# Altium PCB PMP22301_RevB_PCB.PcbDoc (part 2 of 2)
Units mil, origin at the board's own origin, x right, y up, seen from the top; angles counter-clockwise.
Board outline 2805 x 3100 mil, 4 copper layers (Top Layer, Signal Layer 1, Signal Layer 2, Bottom Layer), stack 61.2 mil thick; 104 components, 74 nets, 288 pads, 112 vias.
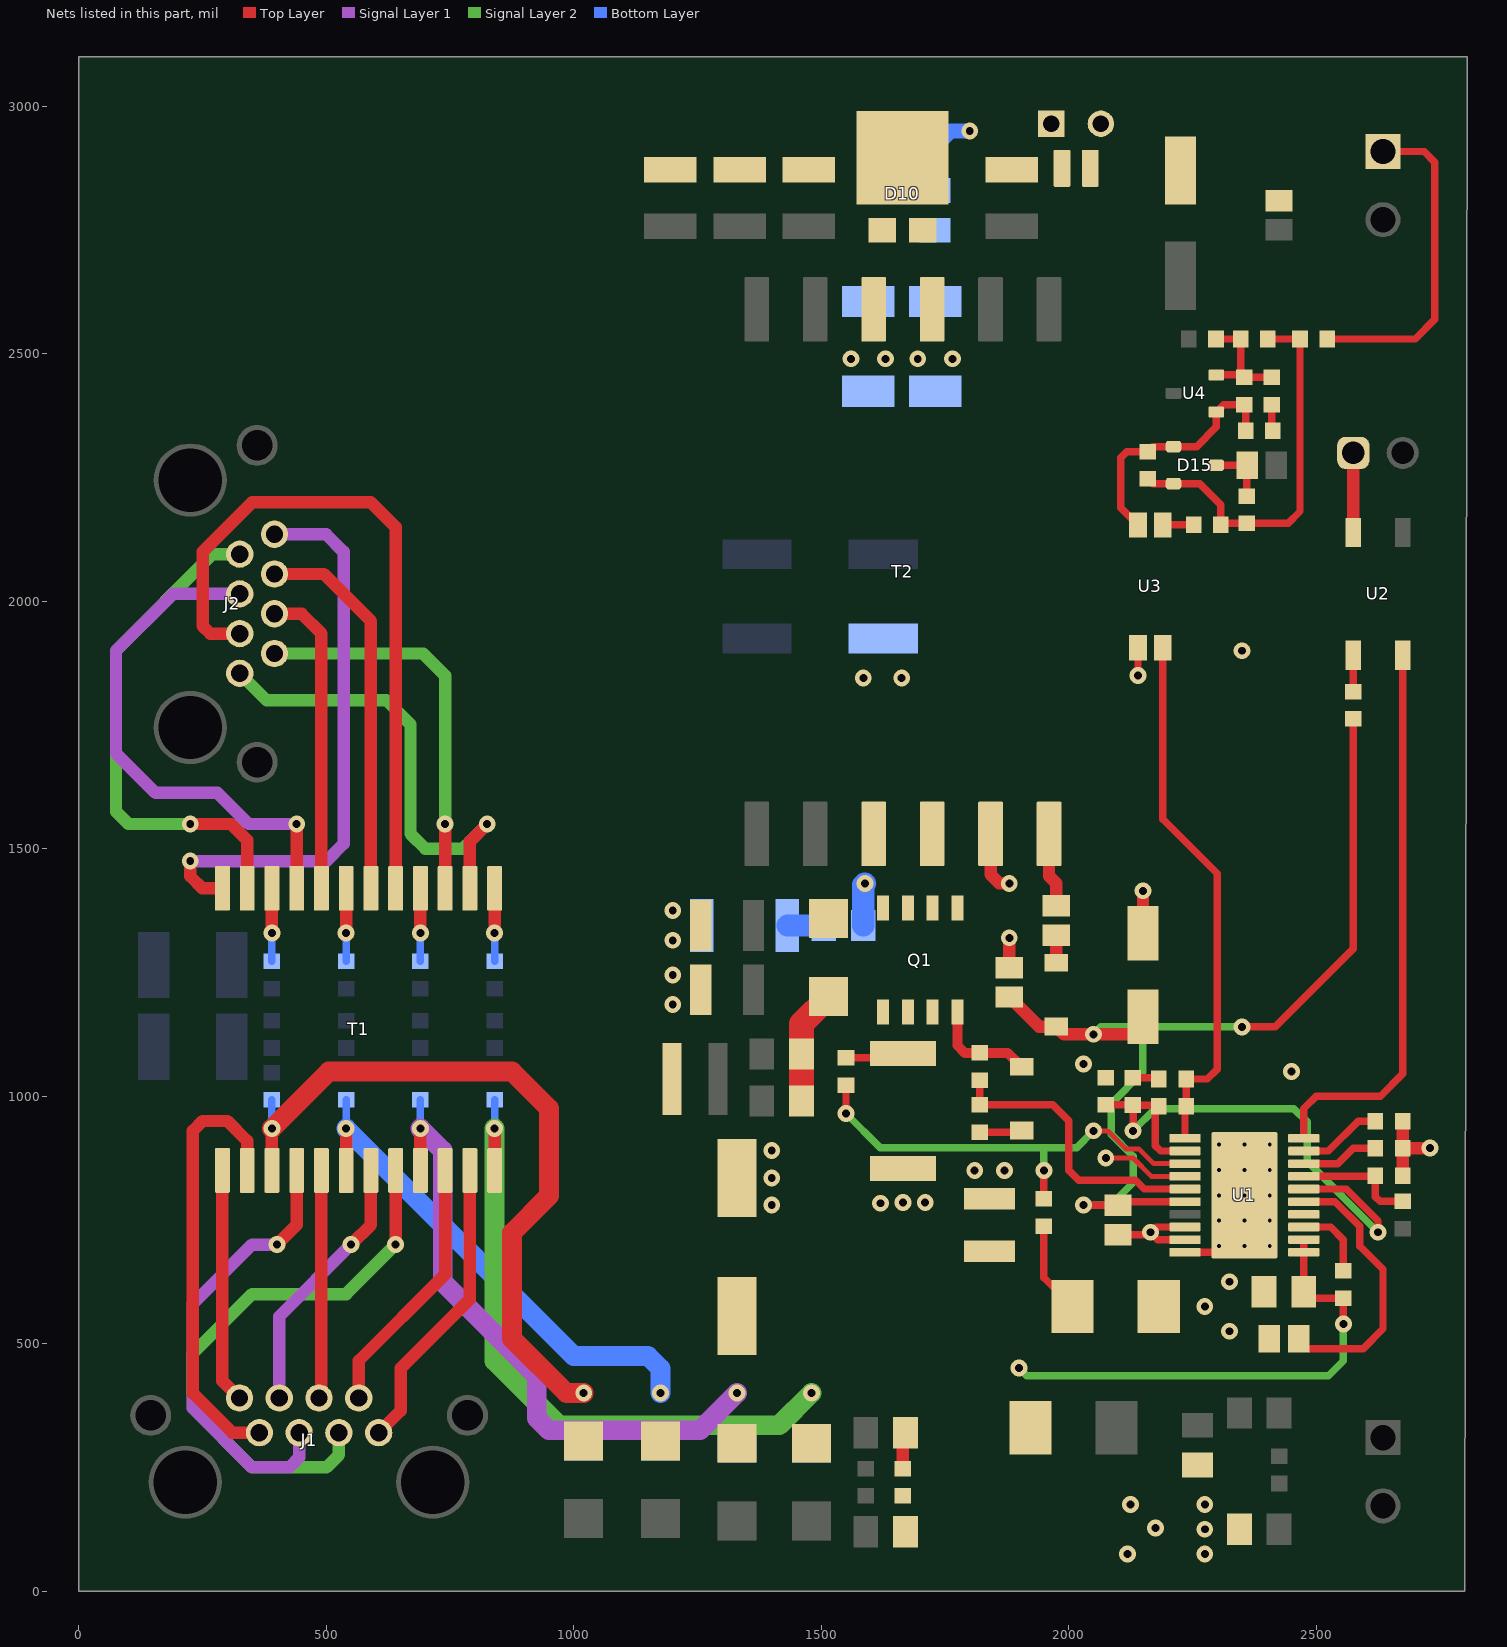
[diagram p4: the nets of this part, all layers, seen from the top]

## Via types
v1: diameter 34, hole 16, Top Layer to Bottom Layer, 97 vias
v2: diameter 19.68, hole 7.87, Top Layer to Bottom Layer, tented both sides, 12 vias
v3: diameter 19.68, hole 7.87, Top Layer to Bottom Layer, 3 vias

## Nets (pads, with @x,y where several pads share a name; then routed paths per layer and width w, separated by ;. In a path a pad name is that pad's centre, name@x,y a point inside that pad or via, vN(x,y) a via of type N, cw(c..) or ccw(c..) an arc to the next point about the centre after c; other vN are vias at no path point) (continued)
NetC12_1: C12.1 C18.2 C19.2 C20.2 C21.2 D10.3 J4.1 L6.1 | length 171.5
  Bottom Layer w30: C12.1@1730,2830 1730,2918.47 1761.53,2950 v1(1800,2950)
NetC12_2: C12.2 R9.2 R10.2
NetC16_1: C16.1 D11.1 R11.1 | length 234
  Top Layer w50: R11.1@1460,990 C16.1@1460,1085 1460,1146.26 D11.1@1515,1201.26
NetC17_1: C17.1 C22.1 J4.2 J5.1 L6.2 R26.2 | length 665.4
  Top Layer w15: R26.2@2522.56,2530 2700,2530 2740,2570 2740,2887.52 2718.62,2908.9 J5.1@2635,2908.9
NetC23_1: C23.1 D11.2 Q1.5 Q1.6 Q1.7 Q1.8 T2.3 T2.4 | length 86.3
  Bottom Layer w45: C23.1@1585,1345 1585,1426.93 v1(1588.07,1430)
NetC23_2: C23.2 R14.2 | length 73.4
  Bottom Layer w45: R14.2@1431.61,1345 C23.2@1505,1345
NetC30_1: C30.1 C32.1 R32.1 R34.1 U4.2 | length 237.3
  Top Layer w15: R34.1@2297.56,2530 R32.1@2347.44,2530 2347.44,2460.12 C30.1@2350.16,2457.4 ; U4.2@2298.31,2457.4 C30.1@2350.16,2457.4 ; C32.1@2410,2452.56 C30.1@2355,2452.56 C30.1@2350.16,2457.4
NetC30_2: C30.2 D15.1 R29.2 R33.2 U3.2 U4.1 | length 516.1
  Top Layer w15: U3.2@2140,2154.02 2105,2189.02 2105,2290 2117.56,2302.56 R29.2@2160,2302.56 2169.84,2312.4 D15.1@2211.69,2312.4 2258.35,2312.4 2298.31,2352.36 U4.1@2298.31,2382.6 2313.15,2397.44 C30.2@2355,2397.44 2357.44,2395 R33.2@2357.44,2345
NetC31_1: C31.1 R30.1 U1.1 U3.4 | length 1088.7
  Top Layer w15: U3.4@2190,1905.98 2190,1560 2300,1450 2300,1054.68 2280,1034.68 C31.1@2237.24,1034.68 R30.1@2237.24,979.68 2234.92,977.36 U1.1@2234.92,914.84
NetC31_2: C31.2 R27.2 | length 53.5
  Top Layer w15: R27.2@2129.69,1037.24 2179.57,1037.24 C31.2@2182.13,1034.68
NetC32_2: C32.2 R33.1 | length 53.5
  Top Layer w15: C32.2@2410,2397.44 2410,2347.56 R33.1@2412.56,2345
NetC33_1: C33.1 D15.3 R28.1 | length 124.8
  Top Layer w15: D15.3@2298.31,2275 C33.1@2360.47,2275 2360,2274.53 R28.1@2360,2212.56
NetD10_1: D10.1 D10.2 R9.1 R10.1 T2.9 T2.10
  other v1: 1560,2490 1630,2490 1695,2490 1765,2490
NetD12_1: D12.1 R15.2 | length 86.3
  Top Layer w15: R15.2@1820,927.44 1901.91,927.44 D12.1@1905,930.53
NetD12_2: D12.2 Q1.4 R12.2 | length 215.2
  Top Layer w20: Q1.4@1775,1169.88 1775,1102.56 1790,1087.56 R12.2@1820,1087.56 1876.91,1087.56 D12.2@1905,1059.47
NetD13_2: D13.2 R13.2 | length 56
  Top Layer w25: D13.2@1975,1269.47 R13.2@1975,1325.47
NetD15_2: D15.2 R26.1 R28.2 R29.1 R31.2 R32.2 | length 793.6
  Top Layer w15: R29.1@2160,2247.44 2169.84,2237.6 D15.2@2211.69,2237.6 2265,2237.6 2307.56,2195.04 R31.2@2307.56,2155 2310,2157.44 R28.2@2360,2157.44 2443.43,2157.44 2467.44,2181.46 R26.1@2467.44,2530 R32.2@2402.56,2530
NetJ1_1: J1.1 T1.23 | length 606.3
  Top Layer w25: J1.1@605.63,320 650,364.37 650,450 790,590 T1.23@790,849.96
NetJ1_2: J1.2 T1.22 | length 532.2
  Top Layer w25: J1.2@565.47,390.08 565.47,465.47 740,640 T1.22@740,849.96
NetJ1_3: J1.3 T1.20 | length 1161.3
  Top Layer w25: v1(640,700) T1.20@640,849.96
  Signal Layer 2 w25: J1.3@525.31,320 525.31,275.31 500,250 350,250 230,370 230,480 350,600 540,600 v1(640,700)
NetJ1_4: J1.4 T1.17 | length 461.9
  Top Layer w25: J1.4@485.16,390.08 490,394.92 T1.17@490,849.96
NetJ1_5: J1.5 T1.16 | length 919.2
  Top Layer w25: v1(400,700) 440,740 T1.16@440,849.96
  Signal Layer 1 w25: v1(400,700) 350,700 230,580 230,370 350,250 425,250 445,270 J1.5@445,320
NetJ1_6: J1.6 T1.19 | length 536.6
  Top Layer w25: v1(550.04,700) 590,739.96 T1.19@590,849.96
  Signal Layer 1 w25: J1.6@404.84,390.08 404.84,554.8 v1(550.04,700)
NetJ1_7: J1.7 T1.14 | length 892.7
  Top Layer w25: T1.14@340,849.96 340,910 300,950 250,950 230,930 230,400 310,320 J1.7@364.68,320
NetJ1_8: J1.8 T1.13 | length 474.2
  Top Layer w25: T1.13@290,849.96 290,424.61 J1.8@324.53,390.08
NetJ2_1: J2.1 T1.2 | length 941.6
  Top Layer w25: T1.2@790,1420.04 790,1515 v1(825,1550)
  Signal Layer 2 w25: J2.1@325,1854.37 379.37,1800 621.3,1800 670,1751.3 670,1530 700,1500 775,1500 v1(825,1550)
NetJ2_2: J2.2 T1.3 | length 793.3
  Top Layer w25: T1.3@740,1420.04 v1(740,1550)
  Signal Layer 2 w25: J2.2@395.08,1894.53 695.47,1894.53 740,1850 v1(740,1550)
NetJ2_3: J2.3 T1.5 | length 1413.4
  Top Layer w25: J2.3@325,1934.69 265.31,1934.69 250,1950 250,2100 350,2200 590,2200 640,2150 T1.5@640,1420.04
NetJ2_4: J2.4 T1.8 | length 626.4
  Top Layer w25: J2.4@395.08,1974.84 450.16,1974.84 490,1935 T1.8@490,1420.04
NetJ2_5: J2.5 T1.9 | length 1058.9
  Top Layer w25: T1.9@440,1420.04 v1(440,1550)
  Signal Layer 1 w25: J2.5@325,2015 190,2015 75,1900 75,1692.83 155,1612.83 280,1612.83 342.83,1550 v1(440,1550)
NetJ2_6: J2.6 T1.6 | length 774.3
  Top Layer w25: J2.6@395.08,2055.16 494.84,2055.16 590,1960 T1.6@590,1420.04
NetJ2_7: J2.7 T1.11 | length 1042.3
  Top Layer w25: v1(225,1550) 307.63,1550 340,1517.63 T1.11@340,1420.04
  Signal Layer 2 w25: v1(225,1550) 100,1550 75,1575 75,1900 270.32,2095.32 J2.7@325,2095.32
NetJ2_8: J2.8 T1.12 | length 1174.8
  Top Layer w25: v1(225,1475) 225,1444.37 249.33,1420.04 T1.12@290,1420.04
  Signal Layer 1 w25: v1(225,1475) 500,1475 535,1510 535,2100 499.53,2135.47 J2.8@395.08,2135.47
NetJ6_1: J6.1 U2.4 | length 161
  Top Layer w25: U2.4@2575,2139.02 J6.1@2575,2300
NetQ1_1: Q1.1 Q1.2 Q1.3 R17.1 R18.2 | length 118.6
  Top Layer w15: R18.2@1550,1077.56 1656.42,1077.56 R17.1@1665,1086.14
NetR1_1: R1.1 T1.1 | length 147.5
  Top Layer w25: v1(840,1330) T1.1@840,1420.04
  Bottom Layer w15: R1.1@840,1272.56 v1(840,1330)
NetR2_1: R2.1 T1.4 | length 147.5
  Top Layer w25: v1(690,1330) T1.4@690,1420.04
  Bottom Layer w15: R2.1@690,1272.56 v1(690,1330)
NetR3_1: R3.1 T1.7 | length 147.5
  Top Layer w25: v1(540,1330) T1.7@540,1420.04
  Bottom Layer w15: R3.1@540,1272.56 v1(540,1330)
NetR8_2: R8.2 T1.10 | length 147.5
  Top Layer w25: v1(390,1330) T1.10@390,1420.04
  Bottom Layer w15: R8.2@390,1272.56 v1(390,1330)
NetR12_1: R12.1 R15.1 U1.5 | length 593.8
  Top Layer w15: R12.1@1820,1032.44 R15.1@1820,982.56 1967.44,982.56 2000,950 2000,850 2020,830 2135,830 2152.52,812.48 U1.5@2234.92,812.48
NetR13_1: R13.1 T2.6 | length 151.7
  Top Layer w25: T2.6@1960.28,1530.08 1960.28,1444.72 1975,1430 R13.1@1975,1384.53
NetR16_1: R16.1 R20.1 U1.17 | length 246.1
  Top Layer w15: U1.17@2475.08,838.07 2618.78,838.07 R20.1@2619.57,838.86 2619.57,796.93 2628.94,787.56 R16.1@2675,787.56
NetR18_1: R18.1 R21.1 U1.3 | length 917
  Top Layer w10: v1(2050,930) 2078.9,930 2116.02,892.87 2142.6,892.87 2171.81,863.66 U1.3@2234.92,863.66
  Top Layer w15: v1(1550,965) R18.1@1550,1022.44 ; R21.1@1950,792.56 v1(1950,850)
  Signal Layer 2 w15: v1(1550,965) 1618.84,896.16 1947.5,896.16 ; v1(1950,850) 1950,893.66 1947.5,896.16 ; v1(2050,930) 2016.16,896.16 1947.5,896.16
NetR19_1: R19.1 U1.19 | length 169.5
  Top Layer w15: U1.19@2475.08,889.25 2524.25,889.25 2584.68,949.68 R19.1@2619.57,949.68
NetR22_2: R22.2 U1.18 | length 157.3
  Top Layer w15: U1.18@2475.08,863.66 2543.66,863.66 2574.68,894.68 R22.2@2619.57,894.68
NetR23_1: R23.1 U1.15 | length 555.4
  Top Layer w15: R23.1@2464.53,510 2484.53,490 2595,490 2635,530 2635,650 2587.8,697.2 2587.8,737.2 2538.11,786.89 U1.15@2475.08,786.89
NetR24_1: R24.1 U2.1 | length 73.4
  Top Layer w15: R24.1@2575,1817.56 U2.1@2575,1890.98
NetR25_1: R25.1 U1.13 | length 153.2
  Top Layer w15: U1.13@2475.08,735.71 2529.29,735.71 2554.69,710.31 R25.1@2554.69,647.24
NetR31_1: R31.1 U3.1 | length 62.8
  Top Layer w15: U3.1@2190,2154.02 2190.98,2155 R31.1@2252.44,2155
PGND: C7.1 C13.2 C14.2 C15.2 C24.2 C25.1 C26.2 C27.2 C28.2 C34.2 L3.1 R14.1 R17.2 R19.2 R20.2 R22.1 T2.5 U1.4 U1.8 U1.9 U3.3 | length 888.5
  Top Layer w10: v1(2075,875) 2130,875 2166.93,838.07 U1.4@2234.92,838.07
  Top Layer w15: C28.2@2099.69,720.16 2160.16,720.16 v1(2165,725) ; v1(2140,1850) U3.3@2140,1905.98 ; U1.9@2234.92,710.12 2179.88,710.12 v1(2165,725) ; U1.8@2234.92,735.71 2175.71,735.71 v1(2165,725)
  Top Layer w25: T2.5@1842.17,1530.08 1842.17,1447.83 1860,1430 v1(1880,1430) ; C26.2@1880,1259.53 v1(1880,1320) ; C27.2@2150,1329.65 v1(2150,1415) ; R20.2@2674.69,838.86 R22.1@2674.69,894.68 ; R19.2@2674.69,949.68 R22.1@2674.69,894.68 ; v1(2730,895) 2675,895 R22.1@2674.69,894.68
  other v1: 2275,75 2275,125 2275,175 1400,780 1620,783.7 1665,785 1710,785 1400,835 1810,850 1870,850 1400,890 2450,1050 2030,1065 1200,1185 1200,1245 1200,1315 1200,1375 1585,1845 1662.5,1845 2350,1900
PPD: U1.14
PR12: C2.2 D2.2 D6.1 T1.24 | length 1333.3
  Top Layer w25: T1.24@840,849.96 v1(840,935)
  Signal Layer 2 w40: v1(840,935) 840,465 970,335 1415,335 v1(1480,400)
  Bottom Layer w15: v1(840,935) C2.2@840,992.44
PR36: C3.2 D3.2 D7.1 T1.21 | length 1271.2
  Top Layer w25: T1.21@690,849.96 v1(690,935)
  Signal Layer 1 w40: v1(690,935) 735,890 735,625 925.04,434.96 925.04,349.96 950,325 1255,325 v1(1330,400)
  Bottom Layer w15: v1(690,935) C3.2@690,992.44
PR45: C4.2 D5.2 D9.1 T1.18 | length 1028.4
  Top Layer w25: T1.18@540,849.96 v1(540,935)
  Bottom Layer w15: v1(540,935) C4.2@540,992.44
  Bottom Layer w40: v1(540,935) 1000,475 1150,475 1175,450 v1(1175,400)
PR78: C5.2 D4.2 D8.1 T1.15 | length 1467.8
  Top Layer w25: T1.15@390,849.96 v1(390,935)
  Top Layer w40: v1(390,935) 505,1050 875,1050 950,975 950,798.9 875,723.9 875,510 985,400 v1(1020,400)
  Bottom Layer w15: v1(390,935) C5.2@390,992.44
T2P: U1.20 U2.2 | length 1139.1
  Top Layer w15: U1.20@2475.08,914.84 2475.08,975.08 2500,1000 2630,1000 2675,1045 U2.2@2675,1895
VB: C25.2 R27.1 R30.2 U1.2 U1.16 | length 1169.2
  Top Layer w15: C25.2@2075,982.44 2129.37,982.44 R27.1@2129.69,982.13 ; v1(2130,930) 2130,981.81 R27.1@2129.69,982.13 ; U1.2@2234.92,889.25 2185.75,889.25 2175,900 2175,977.44 2179.69,982.13 R27.1@2129.69,982.13 ; U1.16@2475.08,812.48 2560.51,812.48 2625,747.99 v1(2625,725)
  Signal Layer 2 w15: v1(2130,930) 2175,975 2455,975 2481.78,948.22 2481.78,868.22 v1(2625,725)
VC: C26.1 C27.1 C28.1 D13.1 R24.2 U1.6 | length 2072.9
  Top Layer w15: v1(2030,780) C28.1@2098.9,780 ; C28.1@2107.36,786.89 U1.6@2234.92,786.89 ; v1(2350,1140) 2417.34,1140 2575,1297.66 R24.2@2575,1762.44
  Top Layer w25: C26.1@1880,1200.47 1939.94,1140.53 D13.1@1975,1140.53 1990.53,1125 v1(2050,1125) 2150,1125 C27.1@2150,1160.35
  Signal Layer 2 w15: v1(2030,780) 2085,780 2130,825 2130,878.9 2085.84,923.06 2085.84,984.97 2150,1049.13 2150,1140 ; v1(2050,1125) 2065,1140 2150,1140 ; v1(2350,1140) 2150,1140
VDD: C10.1 C13.1 C29.2 C34.1 D1.1 D14.1 L1.2 L5.1 R21.2 R25.2 U1.11 U1.12 | length 1240.2
  Top Layer w15: R21.2@1950,737.44 1950,632.99 D14.1@2007.99,575 ; U1.12@2475.08,710.12 U1.11@2475.08,684.53 2475.08,605.08 C29.2@2474.69,604.68 2487.24,592.13 R25.2@2554.69,592.13 2555,591.81 v1(2555,540)
  Top Layer w25: C10.1@1665,248.05 L1.2@1665,309.53
  Signal Layer 2 w15: v1(1899.68,450.49) 1915.17,435 2525,435 2555,465 v1(2555,540)
VSS: C10.2 C29.1 D14.2 L4.2 R23.2 U1.10 U1.21 | length 221.5
  Top Layer w15: U1.10@2234.92,684.53 2235.39,685 2325,685 2320,690 2320,745 2355,780 v3(2355,799.68)
  other v1: 2118.98,75 2175.24,127.2 2125,175 2325,525 2275,575 2325,625
  other v2: 2303.82,697.32 2355,697.32 2406.18,697.32 2303.82,748.5 2406.18,748.5 2303.82,799.68 2406.18,799.68 2303.82,850.87 2406.18,850.87 2303.82,902.05 2355,902.05 2406.18,902.05
  other v3: 2355,748.5 2355,850.87
pads on no net: T2.7 T2.8 U1.7

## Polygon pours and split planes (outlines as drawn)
GND on Bottom Layer "BOTTOM_LAYER_GND_P110" (solid, remove dead copper, pour order 110): 1100,2065 1100,3050 2750,3050 2750,2065
BSP on Bottom Layer "BOTTOM_LAYER_BSP_P116" (solid, remove dead copper, pour order 116): 850,60 850,2450 60,2450 60,60
PGND on Bottom Layer "BOTTOM_LAYER_PGND_P106" (solid, remove dead copper, pour order 106): 1250,450 1100,600 1100,1955 2750,1955 2750,425 2370,425 2370,50 1645,50 1645,450
NetC12_2 on Bottom Layer "BOTTOM_LAYER_NETC12_2_P101" (solid, remove dead copper, pour order 101): 1790,2700 1765,2700 1765,2775 1565,2775 1565,2645 1540,2645 1540,2570 1790,2570
NetD10_1 on Bottom Layer "BOTTOM_LAYER_NETD10_1_P100" (solid, remove dead copper, pour order 100): 1540,2545 1540,2380 1790,2380 1790,2545
VSS on Bottom Layer "BOTTOM_LAYER_VSS_P088" (solid, remove dead copper, pour order 88): 2200,50 2200,475 2420,475 2420,930 2290,930 2290,650 2100,650 2100,50
NetC9_1 on Bottom Layer "BOTTOM_LAYER_NETC9_1_P085" (solid, remove dead copper, pour order 85): 960,50 960,215 1610,215 1610,50
PR12 on Bottom Layer "BOTTOM_LAYER_PR12_P079" (solid, remove dead copper, pour order 79): 1420,250 1540,250 1540,430 1420,430
PR36 on Bottom Layer "BOTTOM_LAYER_PR36_P078" (solid, remove dead copper, pour order 78): 1270,250 1390,250 1390,425 1270,425
PR45 on Bottom Layer "BOTTOM_LAYER_PR45_P077" (solid, remove dead copper, pour order 77): 1115,250 1235,250 1235,425 1115,425
PR78 on Bottom Layer "BOTTOM_LAYER_PR78_P076" (solid, remove dead copper, pour order 76): 960,250 1080,250 1080,425 960,425
GND on Top Layer "TOP_LAYER_GND_P112" (solid, remove dead copper, pour order 112): 1100,3050 2750,3050 2750,2065 1100,2065
BSP on Top Layer "TOP_LAYER_BSP_P114" (solid, remove dead copper, pour order 114): 850,60 60,60 60,2450 850,2450
PGND on Top Layer "TOP_LAYER_PGND_P107" (solid, remove dead copper, pour order 107): 1250,450 1100,600 1100,1955 2750,1955 2750,425 2370,425 2370,50 1645,50 1645,450
NetD10_1 on Top Layer "TOP_LAYER_NETD10_1_P099" (solid, remove dead copper, pour order 99): 1565,2655 1540,2655 1540,2380 1790,2380 1790,2700 1765,2700 1765,2770 1760,2775 1565,2775
NetC17_1 on Top Layer "TOP_LAYER_NETC17_1_P098" (solid, remove dead copper, pour order 98): 2025,2785 2025,3050 2750,3050 2750,2870 2455,2870 2455,2785
NetC12_1 on Top Layer "TOP_LAYER_NETC12_1_P097" (solid, remove dead copper, pour order 97): 1100,2825 1100,3050 2005,3050 2005,2825 1760,2825 1760,2800 1565,2800 1565,2825
NetQ1_1 on Top Layer "TOP_LAYER_NETQ1_1_P096" (solid, remove dead copper, pour order 96): 1740,1195 1740,1000 1595,1000 1595,1195
NetC23_1 on Top Layer "TOP_LAYER_NETC23_1_P095" (solid, remove dead copper, pour order 95): 1550,1600 1550,1410 1455,1410 1455,1300 1600,1300 1600,1225 1805,1225 1805,1410 1770,1410 1770,1600
NetC11_2 on Top Layer "TOP_LAYER_NETC11_2_P094" (solid, remove dead copper, pour order 94): 1270,950 1405,950 1405,1450 1515,1450 1515,1600 1325,1600 1325,1125 1330,1120 1270,1120
AUX on Top Layer "TOP_LAYER_AUX_P093" (solid, remove dead copper, pour order 93): 2030,250 2150,250 2150,310 2370,310 2370,410 2030,410
no net on Top Layer "TOP_LAYER_NONET_P092" (solid, remove dead copper, pour order 92): 2030,250
VDD on Top Layer "TOP_LAYER_VDD_P091" (solid, remove dead copper, pour order 91): 1100,600 1250,450 1645,450 1645,250 2000,250 2000,450 2070,450 2070,655 1900,655 1900,720 1750,720 1750,655 1220,655 1220,1120 1100,1120 1100,800
VSS on Top Layer "TOP_LAYER_VSS_P087" (solid, remove dead copper, pour order 87): 2290,930 2290,650 2100,650 2100,475 2420,475 2420,930
VSS on Top Layer "TOP_LAYER_VSS_P086" (solid, remove dead copper, pour order 86): 1645,215 2200,215 2200,50 1645,50
NetC9_2 on Top Layer "TOP_LAYER_NETC9_2_P084" (solid, remove dead copper, pour order 84): 1615,215 960,215 960,50 1615,50
PR12 on Top Layer "TOP_LAYER_PR12_P083" (solid, remove dead copper, pour order 83): 1420,425 1420,250 1540,250 1540,425
PR36 on Top Layer "TOP_LAYER_PR36_P082" (solid, remove dead copper, pour order 82): 1270,425 1270,250 1390,250 1390,425
PR45 on Top Layer "TOP_LAYER_PR45_P081" (solid, remove dead copper, pour order 81): 1115,425 1115,250 1235,250 1235,425
PR78 on Top Layer "TOP_LAYER_PR78_P080" (solid, remove dead copper, pour order 80): 1080,424.61 1080,250 960,250 960,424.61
NetD10_1 on Signal Layer 1 "SIGNAL_LAYER_1_NETD10_1_P102" (solid, remove dead copper, pour order 102): 1565,2775 1565,2655 1540,2655 1540,2380 1790,2380 1790,2700 1765,2700 1765,2775
GND on Signal Layer 1 "SIGNAL_LAYER_1_GND_P111" (solid, remove dead copper, pour order 111): 1100,2065 2750,2065 2750,3050 1100,3050
no net on Signal Layer 1 "SIGNAL_LAYER_1_NONET_P104" (solid, remove dead copper, pour order 104): 1150,2060
PGND on Signal Layer 1 "SIGNAL_LAYER_1_PGND_P105" (solid, remove dead copper, pour order 105): 1250,450 1100,600 1100,1955 2750,1955 2750,425 2370,425 2370,50 1645,50 1645,450
VSS on Signal Layer 1 "SIGNAL_LAYER_1_VSS_P089" (solid, remove dead copper, pour order 89): 2290,930 2290,650 2250,650 2250,475 2420,475 2420,930
NetD10_1 on Signal Layer 2 "SIGNAL_LAYER_2_NETD10_1_P103" (solid, remove dead copper, pour order 103): 1790,2700 1765,2700 1765,2775 1565,2775 1565,2655 1540,2655 1540,2380 1790,2380
GND on Signal Layer 2 "SIGNAL_LAYER_2_GND_P109" (solid, remove dead copper, pour order 109): 2750,2065 2750,3050 1100,3050 1100,2065
PGND on Signal Layer 2 "SIGNAL_LAYER_2_PGND_P108" (solid, remove dead copper, pour order 108): 1250,450 1100,600 1100,1955 2750,1955 2750,425 2370,425 2370,50 1645,50 1645,450
VSS on Signal Layer 2 "SIGNAL_LAYER_2_VSS_P090" (solid, remove dead copper, pour order 90): 2290,930 2290,650 2250,650 2250,475 2420,475 2420,930

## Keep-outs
Keep-Out Layer:
  text ".Layer_Name" at 577,-858.49 h60

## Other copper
Top Layer:
  rectangle net PGND: 2155,705.39 2229.02,740
  text ".Layer_Name" at 577,-858.49 h60
Bottom Layer:
  text ".Layer_Name" at 577,-858.49 h60

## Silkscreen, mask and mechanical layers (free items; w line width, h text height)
Top Overlay:
  text "'.PRJ_Number'.PCB_Rev" at 85,2940 h108.27
  text ".Layer_Name" at 577,-858.49 h60
Bottom Overlay:
  text ".Layer_Name" at 577,-858.49 h60
Top Paste:
  text ".Layer_Name" at 577,-858.49 h60
Bottom Paste:
  text ".Layer_Name" at 577,-858.49 h60
Top Solder:
  text ".Layer_Name" at 577,-858.49 h60
  text ".Layer_Name" at 577,-858.49 h60
Bottom Solder:
  text ".Layer_Name" at 577,-858.49 h60
Drill Guide:
  text ".Layer_Name" at 577,-858.49 h60
M1 Board Outline:
  the board outline again, w10
  text ".Layer_Name" at 577,-858.49 h60
M2 Board Dimensions:
  rectangle: 0,-275 125,-150
  rectangle: 125,-400 500,-275
  lines w7: 0,-275 1000,-275 ; 125,-400 125,-150 ; 250,-400 250,-150 ; 500,-400 500,-150 ; 750,-400 750,-150 ; 0,-400 1000,-400 1000,-150 0,-150 0,-400
  text ".Layer_Name" at 577,-858.49 h60
M3 3D STEP Top:
  text ".Layer_Name" at 577,-858.49 h60
M4 3D STEP Bottom:
  text ".Layer_Name" at 577,-858.49 h60
M5 Assembly Top:
  lines w10: -292,-930.17 6308,-930.17 ; -292,-726.83 6310,-726.83 ; -292,-523.5 -292,-1133.5 3713,-1133.5 6310,-1133.5 6310,-523.5 -291.5,-523.5 -291.5,-1133.5 1284,-1133.5 ; 2173,-1133.5 2173,-523.5 ; 3440,-726.83 3440,-523.5 ; 4280,-726.83 4280,-523.5 ; 4902,-1140 4902,-937.17
  text "COMPONENTS MARKED 'DNP' SHOULD NOT BE POPULATED." at 1153.5,-318.5 h60
  text "ASSEMBLY VARIANT:" at 1153,-434 h60
  text ".VariantName" at 2189,-434 h60
  text "PCB VIEWED FROM TOP SIDE" at -228.5,-655.67 h60
  text "BOARD #:" at 2248,-655.67 h60
  text ".PRJ_Number" at 2793.5,-655.67 h60
  text "REV:" at 3638,-655.67 h60
  text ".PCB_Rev" at 3929.5,-655.67 h60
  text "SVN REV:" at 4476,-655.67 h60
  text ".VersionControl_RevNumber" at 4982,-655.67 h60
  text "TID #:" at 2248,-859 h60
  text ".TID" at 2793.5,-859 h60
  text "PLOT NAME =" at -228.5,-1064.34 h60
  text ".plot_File_Name" at 577,-1064.34 h60
  text "GENERATED    :" at 2250,-1064.34 h60
  text ".Print_Date" at 3119.5,-1064.34 h60
  text ".Print_Time" at 3848.5,-1064.34 h60
  text "TEXAS INSTRUMENTS" at 5113,-1064.34 h60
M6 Assembly Bottom:
  lines w10: -292.5,-727.33 6309.5,-727.33 ; -290.5,-930.67 6309.5,-930.67 ; 1115.5,-1140.5 1115.5,-937.67 ; 1737.5,-727.33 1737.5,-524 ; 2577.5,-727.33 2577.5,-524 ; 3844.5,-1134 3844.5,-524 ; 4733.5,-1134 6309,-1134 6309,-524 -292.5,-524 -292.5,-1134 2304.5,-1134 6309.5,-1134 6309.5,-524
  text "COMPONENTS MARKED 'DNP' SHOULD NOT BE POPULATED." at 6102,-318 h60
  text ".VariantName" at 5058,-434 h60
  text "ASSEMBLY VARIANT:" at 6097,-434 h60
  text ".VersionControl_RevNumber" at 1035.5,-656.17 h60
  text "SVN REV:" at 1541.5,-656.17 h60
  text ".PCB_Rev" at 2088,-656.17 h60
  text "REV:" at 2379.5,-656.17 h60
  text ".PRJ_Number" at 3224,-656.17 h60
  text "BOARD #:" at 3769.5,-656.17 h60
  text "PCB VIEWED FROM BOTTOM SIDE" at 6246,-656.17 h60
  text ".TID" at 3224,-859.5 h60
  text "TID #:" at 3769.5,-859.5 h60
  text "TEXAS INSTRUMENTS" at 904.5,-1064.84 h60
  text ".Print_Time" at 2169,-1064.84 h60
  text ".Print_Date" at 2898,-1064.84 h60
  text "GENERATED    :" at 3767.5,-1064.84 h60
  text ".plot_File_Name" at 5440.5,-1064.84 h60
  text "PLOT NAME =" at 6246,-1064.84 h60
M9 Title Sheet:
  drawing of 57 lines, arcs and shapes, not listed
  text "1" at 739.84,8036.5 h70
  text "2" at 3235.5,8036.5 h70
  text "3" at 5724.84,8036.5 h70
  text "4" at 8231.51,8036.5 h70
  text "5" at 10730.5,8036.5 h70
  text "6" at 13235.5,8036.5 h70
  text "A" at -416.5,6893.5 h70
  text "A" at 14383.5,6893.5 h70
  text "B" at -416.5,4513.5 h70
  text "B" at 14383.5,4513.5 h70
  text "C" at -416.5,2138.5 h70
  text "C" at 14383.5,2138.5 h70
  text "PROJECT TITLE:" at 11343.5,277.5 h45
  text ".PRJ_Title" at 11393.5,144.17 h70
  text "DESIGNED FOR:" at 11343.5,-23.5 h45
  text ".PRJ_Customer" at 11393.5,-163.5 h70
  text "D" at -416.5,-231.5 h70
  text "D" at 14383.5,-231.5 h70
  text "FILE NAME:" at 11343.5,-323.5 h45
  text ".PCB_File_Name_No_Path" at 11393.5,-443.5 h70
  text "Texas Instruments (TI) and/or its licensors do not warrant the accuracy or completeness of this specification" at 6374,-605.34 h45
  text "ENGINEER:" at 11343.5,-613.5 h45
  text "LAYOUT BY:" at 12848.5,-613.5 h45
  text "or any information contained therein. TI and/or its licensors do not warrant that this design will meet" at 6329.01,-718 h45
  text ".PRJ_Engineer" at 11393.5,-768.49 h70
  text ".PCB_Layout" at 12899,-768.49 h70
  text "the specifications, will be suitable for your application or fit for any particular purpose, or will operate in" at 6329.01,-830.67 h45
  text ".Layer_Name" at 577,-858.49 h60
  text "ALTIUM DESIGNER VERSION:" at 12848.5,-923.5 h45
  text "an implementation. TI and/or its licensors do not warrant that the design is production worthy. You should" at 6329.01,-943.33 h45
  text "completely validate and test your design implementation to confirm the system functionality for your application." at 6374,-1056 h45
  text ".print_Scale" at 11393.5,-1056.83 h70
  text ".Application_BuildNumber" at 12899,-1056.83 h70
  text "1" at 739.84,-1263.5 h70
  text "2" at 3235.5,-1263.5 h70
  text "3" at 5724.84,-1263.5 h70
  text "4" at 8231.51,-1263.5 h70
  text "5" at 10730.5,-1263.5 h70
  text "6" at 13235.5,-1263.5 h70
M10 Fab Notes:
  drawing of 189 lines, arcs and shapes, not listed
  text "DESIGN INFORMATION" at 12382.02,6356.17 h60
  text "MIN. TRACK WIDTH:" at 11737.46,6224.05 h60
  text "8" at 12833.7,6224.05 h60
  text "MIL" at 12988.46,6224.05 h60
  text "MIN. CLEARANCE:" at 11737.46,6099.92 h60
  text "0.2" at 12773.7,6099.93 h60
  text "mm" at 12988.46,6099.92 h60
  text "MIN. VIA PAD SIZE:" at 11737.46,5975.8 h60
  text "24" at 12803.71,5975.8 h60
  text "MIL" at 12988.46,5975.8 h60
  text "0.05mm (2MIL)" at 12432.46,5845.9 h60
  text "MINIMUM ANNULAR RING" at 11408.23,5837.67 h60
  text "EXTERNAL" at 13140.46,5837.67 h60
  text "PER" at 11608.23,5727.55 h60
  text "IPC-D-275 CLASS 2 LEVEL C" at 11828.23,5727.54 h60
  text "MIL, HOLES" at 13316.46,5627.07 h60
  text "+/-" at 12924,5618.48 h60
  text "+/-" at 13778,5618.48 h60
  text "REGISTRATION TOLERANCES:" at 11408.23,5617.42 h60
  text "METAL" at 12608,5617.42 h60
  text "5" at 13184.2,5617.42 h60
  text "3" at 14017.2,5617.42 h60
  text "MIL" at 14133.46,5617.42 h60
  text "HOLE SIZE TOLERANCE (UNLESS OTHERWISE SPECIFIED):" at 11408.23,5519.1 h60
  text "+/-" at 13778,5516.23 h60
  text "3" at 14017.2,5515.17 h60
  text "MIL" at 14133.46,5515.17 h60
  text "MATERIAL:" at 11333.46,5377.52 h60
  text "FR-4 High Tg" at 12319.9,5249 h60
  text "X" at 12175.46,5241.01 h60
  text "FR-408" at 11754.46,5236.49 h60
  text "OTHER" at 13242.46,5236.49 h60
  text "62 MIL (1.6mm) +/-10%" at 12074.56,5093.46 h60
  text "X" at 11954.46,5091.01 h60
  text "THICKNESS:" at 11408.23,5085.24 h60
  text "OTHER" at 13359.46,5085.24 h60
  text "TOLERANCE:" at 11408.23,4946.92 h60
  text "X" at 12256.46,4946.92 h60
  text "ANSI IPC-6012 TYPE 3 CLASS 2" at 12434.48,4946.92 h60
  text "OTHER +/-" at 12434.46,4802.73 h60
  text "BOW & TWIST:" at 11408.23,4657.54 h60
  text "X" at 12256.46,4657.54 h60
  text "ANSI IPC-6012 TYPE 3 CLASS 2" at 12434.48,4657.54 h60
  text "OTHER +/-" at 12434.46,4510.85 h60
  text "DRILLING:" at 11333.46,4380.23 h60
  text "NC_DRILL FILES" at 13094.46,4275.04 h60
  text "REFERENCE:" at 11408.23,4271.1 h60
  text "X" at 12065.46,4271.01 h60
  text "AS SHOWN" at 12243.46,4271.1 h60
  text "X" at 12966.46,4271.1 h60
  text "OTHER" at 13392.46,4128.85 h60
  text "PTH COPPER THICKNESS:" at 11407.91,4125.32 h60
  text "X" at 12547.14,4125.32 h60
  text "20-30 um" at 12675.14,4125.32 h60
  text "BOARD FINISH:" at 11333.46,3977.73 h60
  text "SILKSCREEN:" at 11488.68,3867.6 h60
  text "X" at 12446.46,3867.6 h60
  text "TOP" at 12563.46,3867.6 h60
  text "X" at 12956.46,3867.6 h60
  text "BOTTOM" at 13074.46,3867.6 h60
  text "SILKSCREEN COLOR:" at 11488.68,3712.41 h60
  text "X" at 12445.46,3712.41 h60
  text "WHITE" at 12563.46,3712.41 h60
  text "OTHER" at 13074.46,3712.41 h60
  text "X" at 12576.46,3568.96 h60
  text "GREEN" at 12694.46,3568.96 h60
  text "OTHER" at 13312.46,3568.96 h60
  text "SOLDER RESIST COLOR:" at 11488.68,3562.1 h60
  text "X" at 12576.46,3414.71 h60
  text "MATTE" at 12694.46,3414.71 h60
  text "SEMI-GLOSS" at 13312,3414.07 h60
  text "IMMERSION GOLD (ENIG)" at 12394.46,3241.94 h60
  text "ENEPIG" at 13732,3234.72 h60
  text "SURFACE FINISH:" at 11333.46,3233.72 h60
  text "X" at 12216.46,3233.72 h60
  text "IMM. TIN/SILVER OR EQUIV" at 11663,3096.4 h60
  text "OTHER" at 13094.46,3092.47 h60
  text "ARRAY/PANEL:" at 11333.46,2937.09 h60
  text "CUT AND TRIM PER M1 BOARD OUTLINE" at 12394.46,2928.87 h60
  text "X" at 12216.46,2925 h60
  text "N.C. ROUTE" at 12394.46,2792.9 h60
  text "V. SCORE" at 13260.46,2792.9 h60
  text "CERTIFICATION:" at 11333.46,2663.77 h60
  text "MATERIALS AND WORKMANSHIP FOR ALL PCBS" at 12058.46,2663.77 h60
  text "TO MEET OR EXCEED THE REQUIREMENTS OF:" at 12058.46,2569.71 h60
  text "X" at 11695.97,2441.08 h60
  text "ANSI IPC-A-600F CLASS ->" at 11823.96,2441.08 h60
  text "X" at 13471.97,2441.08 h60
  text "2" at 13581.96,2441.08 h60
  text "1" at 13266.96,2439.58 h60
  text "3" at 13935.96,2439.58 h60
  text "X" at 12507.97,2293.39 h60
  text "RoHS" at 12635.96,2293.39 h60
  text "OTHER" at 13280.36,2293.39 h60
  text "PER ORDER" at 13677.42,2293.39 h60
  text "ALL BOARDS MUST MEET OR EXCEED UL94-V0 REQUIREMENTS." at 11361,2139.57 h60
  text "PCB MUST BEAR THE UL94V-0 UL REGISTERED MATERIAL ID NUMBER" at 11361,2023.5 h60
  text "ADDITIONAL REQUIREMENTS:" at 11333.46,1854.08 h60
  text "MICROSECTION:" at 11408.23,1746.95 h60
  text "YES" at 12313.96,1746.95 h60
  text "REQUIRED" at 13175.46,1602.62 h60
  text "BARE BOARD ELEC. TEST:" at 11408.23,1599.76 h60
  text "NONE" at 12713.96,1599.76 h60
  text "X" at 13057.46,1599.76 h60
  text "PER ORDER" at 13767.46,1599.76 h60
  text "XX MIL VIAS REQUIRE NON-CONDUCTIVE FILL AND PLANARIZE" at 11576.38,1394.82 h59
  text "XX MIL VIAS REQUIRE CONDUCTIVE FILL AND PLANARIZE" at 11584.38,1290.84 h60
  text "OUTER XX MIL TRACES REQUIRE 50 OHM SINGLE-ENDED IMPEDANCE" at 11583.39,1127.46 h58
  text "LAYER 2 & 3 (INNER LAYERS) XX MIL WIDE, XX MIL SPACE / TRACES REQUIRE 100 OHM DIFFERENTIAL IMPEDANCE" at 11575.39,891.74 h60
  text ".Layer_Name" at 577,-858.49 h60
M11 Gerber Information:
  lines w10: -292,-930.17 6308,-930.17 ; -292,-726.83 6310,-726.83 ; -292,-523.5 -292,-1133.5 3713,-1133.5 6310,-1133.5 6310,-523.5 -291.5,-523.5 -291.5,-1133.5 1284,-1133.5 ; 2173,-1133.5 2173,-523.5 ; 3440,-726.83 3440,-523.5 ; 4280,-726.83 4280,-523.5 ; 4902,-1140 4902,-937.17
  text "ALL ARTWORK VIEWED FROM TOP SIDE" at -228.5,-655.67 h60
  text "BOARD #:" at 2248,-655.67 h60
  text ".PRJ_Number" at 2793.5,-655.67 h60
  text "REV:" at 3638,-655.67 h60
  text ".PCB_Rev" at 3929.5,-655.67 h60
  text "SVN REV:" at 4476,-655.67 h60
  text ".VersionControl_RevNumber" at 4982,-655.67 h60
  text "LAYER NAME =" at -228.5,-858.49 h60
  text "TID #:" at 2248,-859 h60
  text ".TID" at 2793.5,-859 h60
  text "PLOT NAME =" at -228.5,-1064.34 h60
  text ".plot_File_Name" at 577,-1064.34 h60
  text "GENERATED    :" at 2250,-1064.34 h60
  text ".Print_Date" at 3119.5,-1064.34 h60
  text ".Print_Time" at 3848.5,-1064.34 h60
  text "TEXAS INSTRUMENTS" at 5113,-1064.34 h60
M12 Stackup:
  drawing of 295 lines, arcs and shapes, not listed
  text "Layer" at 9776.2,7835 h60
  text "Name" at 10186.11,7835 h60
  text "Material" at 11125.85,7835 h60
  text "Thickness" at 11985.62,7835 h60
  text "Constant" at 12635.46,7835 h60
  text "Board Layer Stack" at 13205.32,7835 h60
  text "1" at 9776.2,7715 h60
  text "Top Overlay" at 10186.11,7715 h60
  text "2" at 9776.2,7595 h60
  text "Top Solder" at 10186.11,7595 h60
  text "Solder Resist" at 11125.85,7595 h60
  text "0.40mil" at 11985.62,7595 h60
  text "3.5" at 12635.46,7595 h60
  text "3" at 9776.2,7475 h60
  text "Top Layer" at 10186.11,7475 h60
  text "Copper" at 11125.85,7475 h60
  text "2.80mil" at 11985.62,7475 h60
  text "4" at 9776.2,7355 h60
  text "Dielectric 2" at 10186.11,7355 h60
  text "15.00mil" at 11985.62,7355 h60
  text "4.2" at 12635.46,7355 h60
  text "5" at 9776.2,7235 h60
  text "Signal Layer 1" at 10186.11,7235 h60
  text "Copper" at 11125.85,7235 h60
  text "2.80mil" at 11985.62,7235 h60
  text "6" at 9776.2,7115 h60
  text "Dielectric 3" at 10186.11,7115 h60
  text "20.00mil" at 11985.62,7115 h60
  text "4.2" at 12635.46,7115 h60
  text "7" at 9776.2,6995 h60
  text "Signal Layer 2" at 10186.11,6995 h60
  text "Copper" at 11125.85,6995 h60
  text "2.80mil" at 11985.62,6995 h60
  text "8" at 9776.2,6875 h60
  text "Dielectric1" at 10186.11,6875 h60
  text "FR-4" at 11125.85,6875 h60
  text "15.00mil" at 11985.62,6875 h60
  text "4.8" at 12635.46,6875 h60
  text "9" at 9776.2,6755 h60
  text "Bottom Layer" at 10186.11,6755 h60
  text "Copper" at 11125.85,6755 h60
  text "2.80mil" at 11985.62,6755 h60
  text "10" at 9776.2,6635 h60
  text "Bottom Solder" at 10186.11,6635 h60
  text "Solder Resist" at 11125.85,6635 h60
  text "0.40mil" at 11985.62,6635 h60
  text "3.5" at 12635.46,6635 h60
  text "11" at 9776.2,6515 h60
  text "Bottom Overlay" at 10186.11,6515 h60
  text ".Layer_Name" at 577,-858.49 h60
M13 Component Bodies Top:
  text ".Layer_Name" at 577,-858.49 h60
M14 Component Bodies Bottom:
  text ".Layer_Name" at 577,-858.49 h60
M15 Courtyards Top:
  text ".Layer_Name" at 577,-858.49 h60
M16 Courtyards Bottom:
  text ".Layer_Name" at 577,-858.49 h60
Drill Drawing:
  lines w10: 3130.98,228.02 3144.76,228.02 3144.76,214.23 3172.32,214.23 3172.32,228.02 3186.1,228.02 3186.1,255.58 3172.32,255.58 3172.32,269.36 3144.76,269.36 3144.76,255.58 3130.98,255.58 3130.98,228.02 ; 3130.98,338.26 3158.54,352.04 3186.1,338.26 3172.32,365.82 3186.1,393.38 3158.54,379.6 3130.98,393.38 3144.76,365.82 3130.98,338.26 ; 3130.98,517.41 3186.1,517.41 3158.54,462.29 3130.98,517.41 ; 3130.98,600.1 3144.76,600.1 3158.54,586.32 3172.32,600.1 3186.1,600.1 3172.32,613.88 3186.1,627.66 3172.32,627.66 3158.54,641.44 3144.76,627.66 3130.98,627.66 3144.76,613.88 3130.98,600.1 ; 3130.98,710.34 3130.98,724.12 3144.76,737.9 3130.98,751.68 3130.98,765.46 3144.76,765.46 3158.54,751.68 3172.32,765.46 3186.1,765.46 3186.1,751.68 3172.32,737.9 3186.1,724.12 3186.1,710.34 3172.32,710.34 3158.54,724.12 3144.76,710.34 3130.98,710.34 ; 3130.98,834.37 3186.1,834.37 3186.1,889.49 3130.98,889.49 3130.98,834.37 ; 3130.98,958.4 3186.1,958.4 3186.1,1013.52 3130.98,1013.52 3130.98,958.4 ; 3130.98,1109.98 3158.54,1082.42 3186.1,1109.98 3158.54,1137.54 3130.98,1109.98 ; 3142,969.42 3175.08,969.42 3175.08,1002.49 3142,1002.49 3142,969.42
  lines w12: 3081,177.03 6307.8,177.03 ; 3081,1169.24 6307.8,1169.24 ; 3418.36,53 3418.36,1293.27 ; 3750.06,53 3750.06,1293.27 ; 4385.91,53 4385.91,1293.27 ; 4644.71,53 4644.71,1293.27 ; 5019.46,53 5019.46,1293.27 ; 5742,53 5742,1293.27 ; 3081,53 6307.8,53 6307.8,1293.27 3081,1293.27 3081,53
  text "Symbol" at 3155.42,1206.45 h72
  text "Quantity" at 3455.57,1206.45 h72
  text "Finished Hole Size" at 3787.26,1206.45 h72
  text "Plated" at 4423.12,1206.45 h72
  text "Hole Type" at 4681.92,1206.45 h72
  text "Drill Layer Pair" at 5056.67,1206.45 h72
  text "Hole Tolerance" at 5779.21,1206.45 h72
  text "15" at 3455.57,1082.42 h60
  text "7.87mil (0.200mm)" at 3787.26,1082.42 h60
  text "PTH" at 4423.12,1082.42 h60
  text "Round" at 4681.92,1082.42 h60
  text "Top Layer - Bottom Layer" at 5056.67,1082.42 h60
  text "97" at 3455.57,958.4 h60
  text "16.00mil (0.406mm)" at 3787.26,958.4 h60
  text "PTH" at 4423.12,958.4 h60
  text "Round" at 4681.92,958.4 h60
  text "Top Layer - Bottom Layer" at 5056.67,958.4 h60
  text "2" at 3455.57,834.37 h60
  text "33.47mil (0.850mm)" at 3787.26,834.37 h60
  text "PTH" at 4423.12,834.37 h60
  text "Round" at 4681.92,834.37 h60
  text "Top Layer - Bottom Layer" at 5056.67,834.37 h60
  text "16" at 3455.57,710.34 h60
  text "35.04mil (0.890mm)" at 3787.26,710.34 h60
  text "PTH" at 4423.12,710.34 h60
  text "Round" at 4681.92,710.34 h60
  text "Top Layer - Bottom Layer" at 5056.67,710.34 h60
  text "2" at 3455.57,586.32 h60
  text "45.28mil (1.150mm)" at 3787.26,586.32 h60
  text "PTH" at 4423.12,586.32 h60
  text "Round" at 4681.92,586.32 h60
  text "Top Layer - Bottom Layer" at 5056.67,586.32 h60
  text "4" at 3455.57,462.29 h60
  text "51.18mil (1.300mm)" at 3787.26,462.29 h60
  text "PTH" at 4423.12,462.29 h60
  text "Round" at 4681.92,462.29 h60
  text "Top Layer - Bottom Layer" at 5056.67,462.29 h60
  text "4" at 3455.57,338.26 h60
  text "61.81mil (1.570mm)" at 3787.26,338.26 h60
  text "PTH" at 4423.12,338.26 h60
  text "Round" at 4681.92,338.26 h60
  text "Top Layer - Bottom Layer" at 5056.67,338.26 h60
  text "4" at 3455.57,214.23 h60
  text "128.00mil (3.251mm)" at 3787.26,214.23 h60
  text "PTH" at 4423.12,214.23 h60
  text "Round" at 4681.92,214.23 h60
  text "Top Layer - Bottom Layer" at 5056.67,214.23 h60
  text "144 Total" at 3455.57,90.21 h60
  text ".Layer_Name" at 577,-858.49 h60
M17 Embedded Cavity:
  text ".Layer_Name" at 577,-858.49 h60
M18 Embedded Assembly:
  text ".Layer_Name" at 577,-858.49 h60
M19 Embedded Keepout:
  text ".Layer_Name" at 577,-858.49 h60

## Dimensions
0,-400 to 1000,-400 on M2 Board Dimensions
0,0 to 0,3100 on M2 Board Dimensions
0,0 to 2800,0 on M2 Board Dimensions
